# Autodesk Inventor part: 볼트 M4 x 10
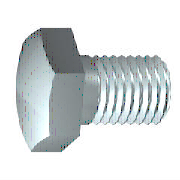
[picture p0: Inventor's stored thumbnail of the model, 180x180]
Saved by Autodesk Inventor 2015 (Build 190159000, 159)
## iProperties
Created: 2012-02
Part Number: 볼트 M4 x 10
Material: 스테인리스강
Description: 6각 머리 나사
Document SubType Name: Modeling
Standard: ISO 4017
Designer: mduedu
Standard Revision: Third edition 1999-08-15
Standards Organization: ISO
Language: ko-KR
Size Designation: M4 x 10
Categories: <MemberInstance><Categories><Category DisplayName="조임쇠" InternalName="e4da775c-781d-43d5-af7c-5136215cf5a6" Mnemonic="FSTN"><Category DisplayName="볼트" InternalN
Density: 8.08 g/cm^3
Appearance: 반광택
Mass: 1.91889 g
Surface Area: 2.7092 cm^2
Volume: 0.237486 cm^3
IsCustomPart: 0
Author: mduedu
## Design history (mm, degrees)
sketch "스케치1"
  geometry: L1 (0, 3.015)-(0, 2); L2 (2.1, 2)-(10, 2); L3 (10, 2)-(10, 0); L4 (10, 0)-(-0.4, 0); L5 (-2.48, 0)-(12.08, 0) reference; L6 (-0.4, 0)-(-0.4, 3.015); L7 (-0.4, 3.015)-(0, 3.015); L8 (2.1, 2)-(1.67, 2); L9 (1.67, 2)-(0, 2); L10 (0, -0.603)-(0, 3.618) reference
  constraints: 16 end point, 2 collinear, 2 perpendicular, 1 parallel
  dimensions: "d0" = 10 distance between parallel lines of L3 L1 (= NLG); "d1" = 7.9 distance from line of L2.start L3 (= GEL); "d2" = 4 diameter of L2 L4 (= GD); "d9" = 0.4001 distance between parallel lines of L6 L1 (computed from SD); "d10" = 6.03 diameter of L7 L4 (= SD2); "d13" = 0.42952 distance of L2.start L8.end (computed from GAL); "d14" = 4 diameter of L9 L4 (= BDM)
revolve "본체" sketch "스케치1" stored, may be unused: angle "d12" = 90 deg
sketch "스케치2"
  geometry: L1 (0, 4.041)-(3.5, 2.021); L2 (3.5, 2.021)-(3.5, -2.021); L3 (3.5, -2.021)-(0, -4.041); L4 (0, -4.041)-(-3.5, -2.021); L5 (-3.5, -2.021)-(-3.5, 2.021); L6 (-3.5, 2.021)-(0, 4.041); 2 further points
  constraints: 12 end point, 1 coincident, 1 vertical, 11 other
  dimensions: "d11" = 7 distance between parallel lines of L5 L2 (= SW)
extrude "머리" join sketch "스케치2" distance "d3" = 2.4 (= KOH - SD); taper "d4" = 0 deg
sketch "스케치4"
  geometry: L1 (-2.8, 3.5)-(-2.8, 4.041); L2 (-2.8, 4.041)-(-2.487, 4.041); L3 (-2.487, 4.041)-(-2.8, 3.5); L4 (-3.28, 0)-(0.08, 0) reference; L5 (-0.4, 4.041)-(-2.8, 4.041) reference; L6 (-2.8, 2.021)-(-2.8, 4.041) reference
  constraints: 6 end point, 2 collinear, 1 perpendicular, 1 vertical
  dimensions: "d5" = 30 deg angle of L3 L1 (= ANG1); "d19" = 7 diameter of L1.start L4 (= SW0)
revolve "모따기1" sketch "스케치4" stored, may be unused: angle "d21" = 90 deg
workplane "Work Plane1"
body "Solid1"
feature "스레드" dims "d15" = 7.9 (= GEL), "d16" = 0
chamfer "모따기2" distance "d6" = 0.42941 (= -0.5 x SPD + 0.5 x GD); stored, may be unused: second distance "d7" = 0.42952 (computed from GUL), angle "d55" = 45 deg
other parameters: "NLG" = 10 [user parameter; used in 1 equation term], "GD" = 4 (= NND) [user parameter; used in 2 equation terms], "BDM" = 4 (= NND) [user parameter; used in 1 equation term], "KOH" = 2.8 [user parameter; used in 1 equation term], "GEL" = 7.9 [user parameter; used in 2 equation terms], "SW" = 7 [user parameter; used in 2 equation terms], "SW0" = 7 (= SW) [user parameter; used in 1 equation term], "SPD" = 3.14117 (= NND - 1.2269 x PTC) [user parameter; used in 1 equation term], "SD2" = 6.03 [user parameter; used in 2 equation terms], "SD" = 0.4 [user parameter; used in 2 equation terms], "ANG1" = 30 deg [user parameter; used in 1 equation term], "GAL" = 0.42941 (= 0.61345 x PTC) [user parameter; used in 1 equation term], "GUL" = 0.42941 (= 0.61345 x PTC) [user parameter; used in 1 equation term], "d8" = 0, "RR" = 0.2 [user parameter], "d57" = 0, "d58" = 0, "TPU" = 14.28571 (computed from PTC) [user parameter], "GD1" = 3.14117 (= THREADDIA - 1.2269 x PTC) [user parameter], "THREADDIA" = 4 [user parameter; used in 1 equation term], "SDH" = 6.03 (= SD2) [user parameter], "SDHG" = 2.1 [user parameter], "TOA" = 30 deg [user parameter], "PTC" = 0.7 [user parameter; used in 5 equation terms], "NND" = 4 [user parameter; used in 3 equation terms], "E0" = 8.085 [user parameter]
